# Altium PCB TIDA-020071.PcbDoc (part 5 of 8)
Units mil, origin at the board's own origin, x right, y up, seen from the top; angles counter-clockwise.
Board outline 5750 x 4050 mil, 6 copper layers (Top Layer, GND PLANE-1, SIGNAL LAYER, SIGNAL/POWER LAYER, GND PLANE-2, Bottom Layer), stack 59.616 mil thick; 776 components, 498 nets, 2205 pads, 871 vias.
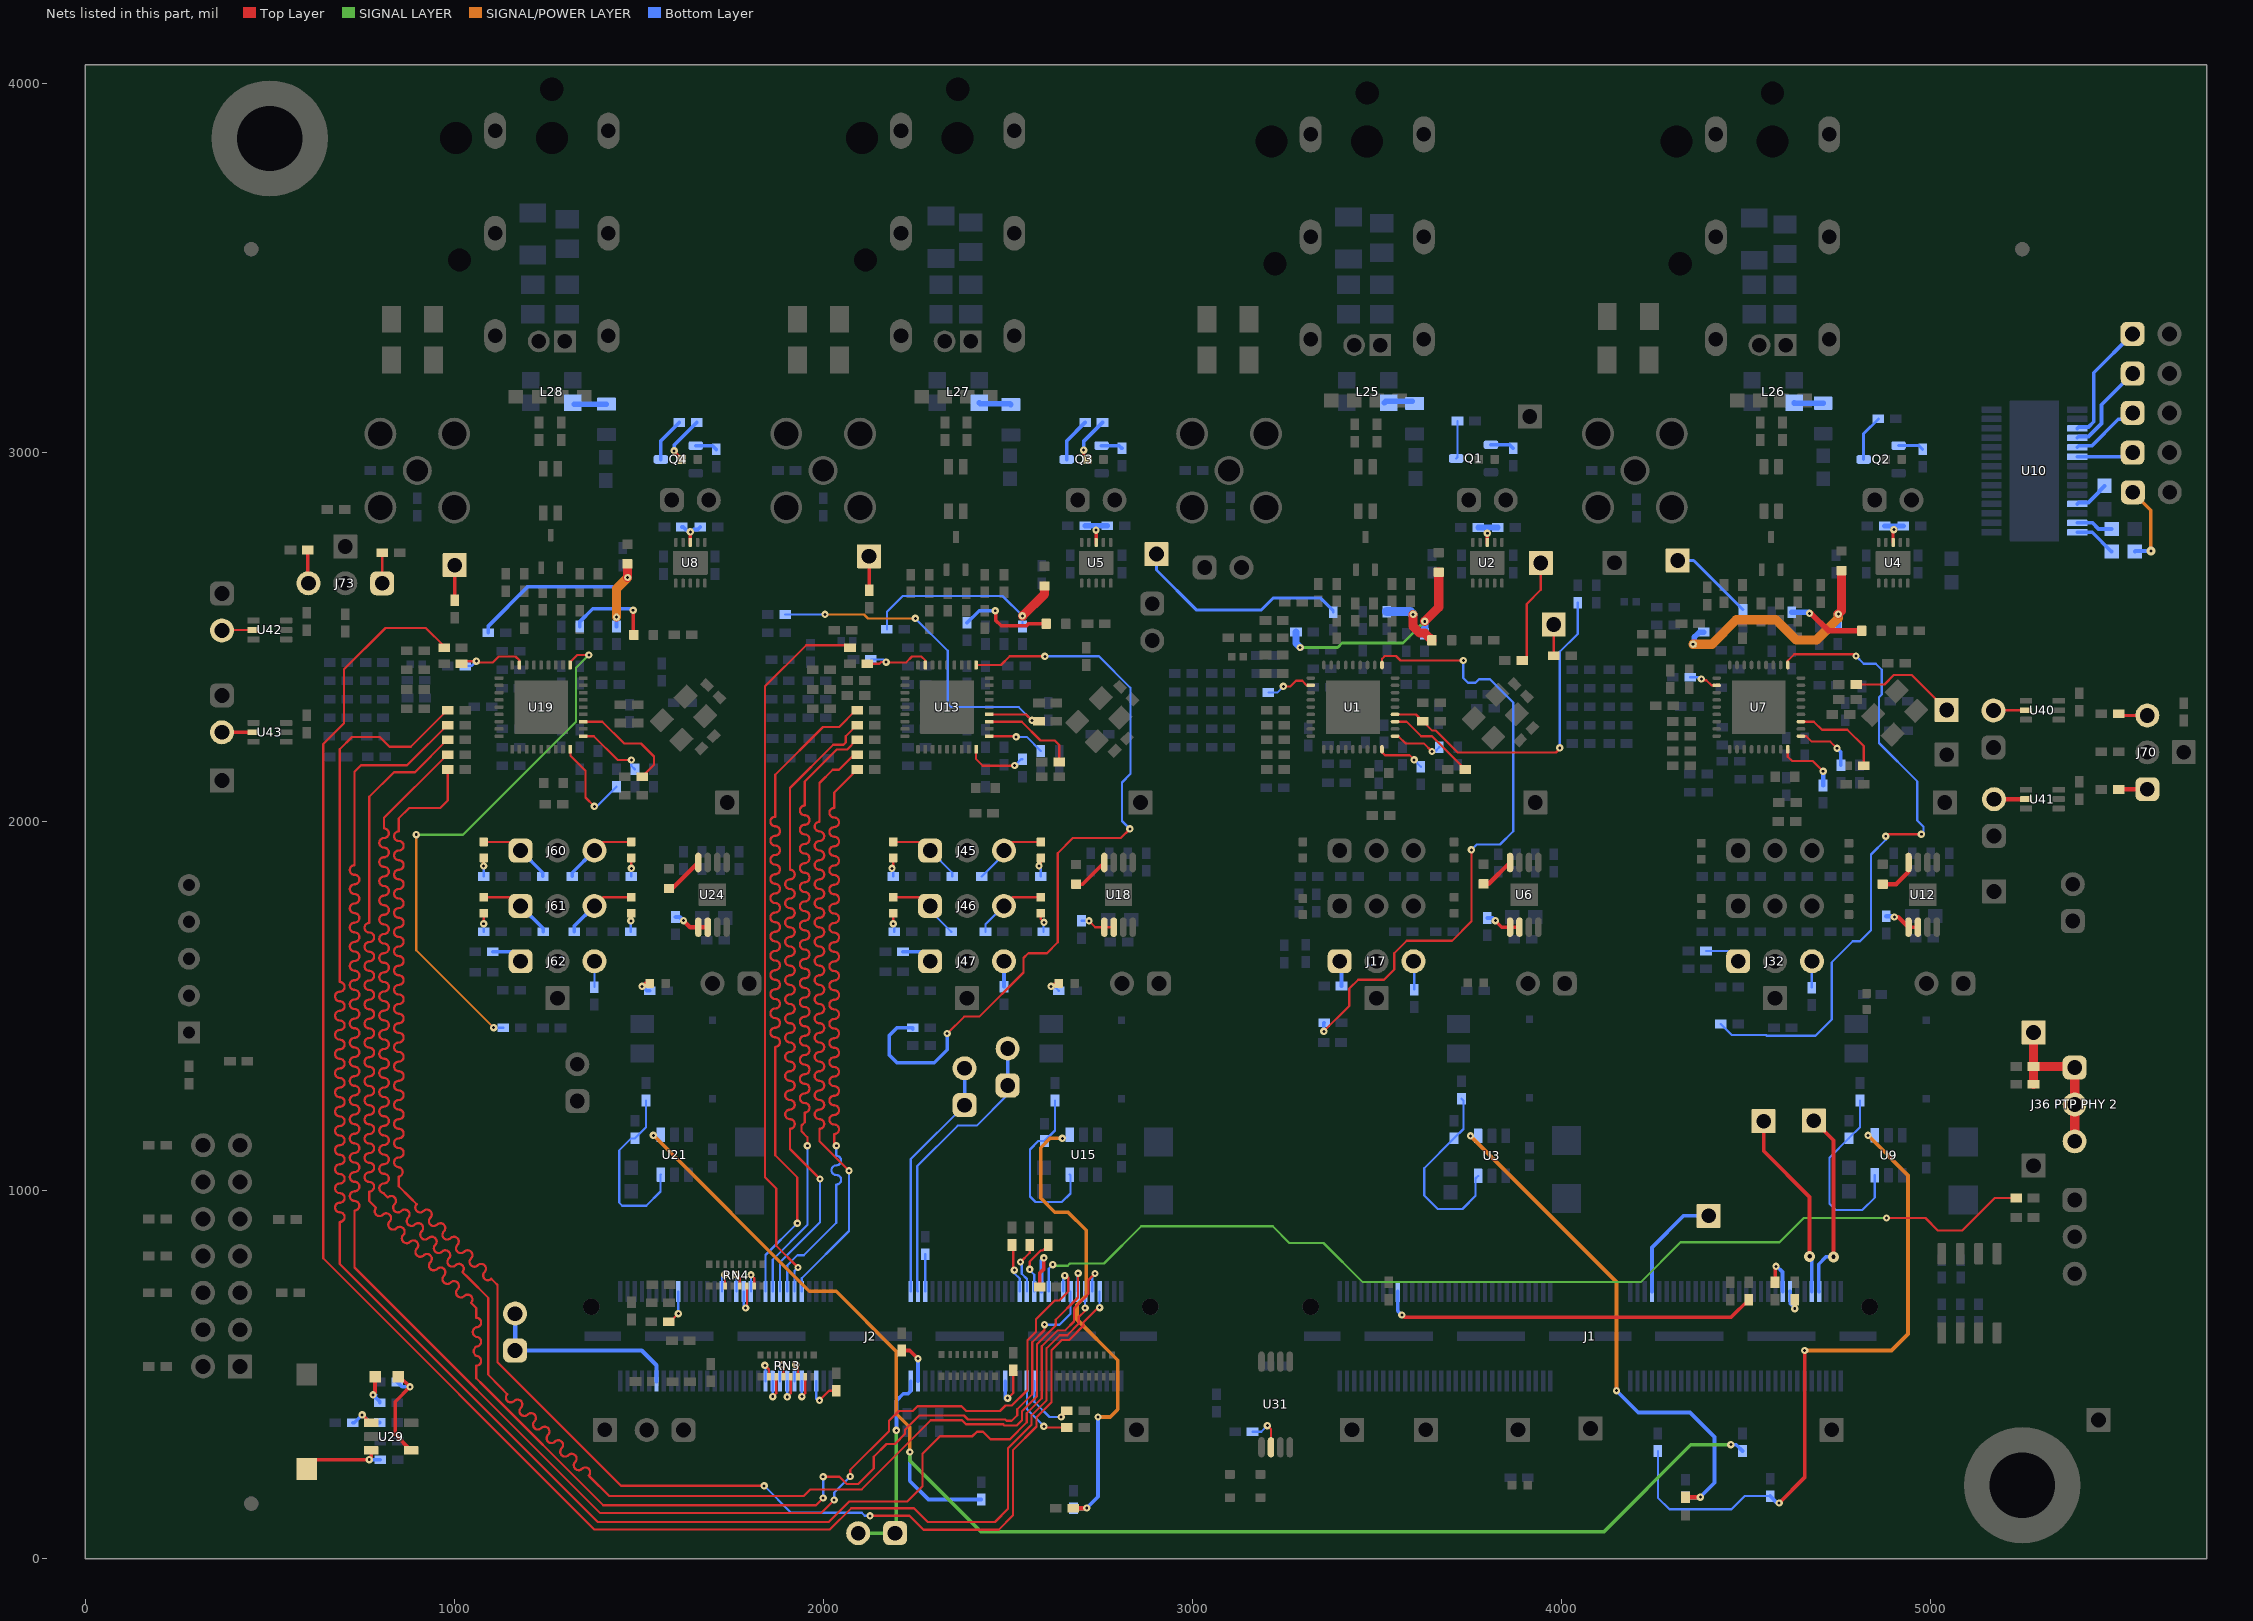
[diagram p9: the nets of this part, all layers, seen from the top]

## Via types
v1: diameter 20, hole 8, Top Layer to Bottom Layer, tented both sides, 637 vias
v2: diameter 30, hole 12, Top Layer to Bottom Layer, tented both sides, 105 vias
v3: diameter 19.68, hole 7.87, Top Layer to Bottom Layer, tented bottom, 68 vias
v4: diameter 19.68, hole 7.87, Top Layer to Bottom Layer, 25 vias
v5: diameter 24, hole 8, Top Layer to Bottom Layer, tented both sides, 24 vias
v6: diameter 19.68, hole 7.87, Top Layer to Bottom Layer, tented both sides, 12 vias

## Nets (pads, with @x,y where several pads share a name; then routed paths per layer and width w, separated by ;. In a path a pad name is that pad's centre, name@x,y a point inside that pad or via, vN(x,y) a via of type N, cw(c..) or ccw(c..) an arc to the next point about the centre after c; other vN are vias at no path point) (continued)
NetD19_2: D19.2 R133.1 | length 49
  Top Layer w6: v1(2618.13,1552) 2626.13,1560 D19.2@2638.49,1560
  Bottom Layer w6: v1(2618.13,1552) 2626.49,1552 R133.1@2638.49,1540
NetD20_1: D20.1 R131.2 | length 125.7
  Top Layer w10: v1(2705.89,3005.12) 2705.89,2990.8 D20.1@2716.69,2980
  Bottom Layer w10: v1(2705.89,3005.12) 2705.89,3028.65 R131.2@2757.24,3080
NetD21_1: D21.1 J45.1 R121.1 | length 204.5
  Top Layer w6: D21.1@2190,1943.31 2266.69,1943.31 J45.1@2290,1920
  Bottom Layer w6: J45.1@2290,1920 2350,1860 R121.1@2350,1850
NetD21_2: D21.2 R122.1 | length 54.7
  Top Layer w6: v1(2186.69,1871.65) 2190,1874.96 D21.2@2190,1900
  Bottom Layer w6: v1(2186.69,1871.65) 2190,1871.65 R122.1@2190,1850
NetD22_1: D22.1 R123.1 | length 54.3
  Top Layer w6: v1(2584.84,1878.62) 2590,1883.78 D22.1@2590,1900
  Bottom Layer w6: v1(2584.84,1878.62) 2584.84,1876.81 2590,1871.65 R123.1@2590,1850
NetD22_2: D22.2 J45.3 R124.1 | length 204.5
  Top Layer w6: J45.3@2490,1920 2513.31,1943.31 D22.2@2590,1943.31
  Bottom Layer w6: R124.1@2430,1850 2490,1910 J45.3@2490,1920
NetD23_1: D23.1 J46.1 R125.1 | length 203.4
  Top Layer w6: D23.1@2190,1793.31 2266.69,1793.31 J46.1@2290,1770
  Bottom Layer w6: J46.1@2290,1770 2290,1757.24 R125.1@2347.24,1700
NetD23_2: D23.2 R126.1 | length 51.1
  Top Layer w6: v1(2190,1721.65) D23.2@2190,1750
  Bottom Layer w6: v1(2190,1721.65) 2192.76,1718.9 R126.1@2192.76,1700
NetD24_1: D24.1 R127.1 | length 54
  Top Layer w6: D24.1@2590,1750 2590,1734.15 v1(2598.49,1725.66)
  Bottom Layer w6: R127.1@2597.24,1700 2597.24,1724.42 v1(2598.49,1725.66)
NetD24_2: D24.2 J46.3 R128.1 | length 200.4
  Top Layer w6: J46.3@2490,1770 2513.31,1793.31 D24.2@2590,1793.31
  Bottom Layer w6: R128.1@2440,1700 2440,1720 J46.3@2490,1770
NetD27_2: D27.2 R186.1 | length 49
  Top Layer w10: v1(1509.64,1552) 1517.64,1560 D27.2@1530,1560
  Bottom Layer w10: v1(1509.64,1552) 1521.63,1540 R186.1@1530,1540
NetD28_1: D28.1 R184.2 | length 133.8
  Top Layer w10: v1(1596.2,3003.44) 1596.2,3000.5 D28.1@1616.69,2980
  Bottom Layer w10: v1(1596.2,3003.44) 1596.2,3018.95 R184.2@1657.24,3080
NetD29_1: D29.1 J60.1 R174.1 | length 204.5
  Top Layer w6: D29.1@1080,1943.31 1156.69,1943.31 J60.1@1180,1920
  Bottom Layer w10: J60.1@1180,1920 1240,1860 R174.1@1240,1850
NetD29_2: D29.2 R175.1 | length 50
  Top Layer w6: v1(1080,1878.17) D29.2@1080,1900
  Bottom Layer w6: R175.1@1080,1850 v1(1080,1878.17)
NetD30_1: D30.1 R176.1 | length 50
  Top Layer w6: v1(1480,1871.65) D30.1@1480,1900
  Bottom Layer w6: R176.1@1480,1850 v1(1480,1871.65)
NetD30_2: D30.2 J60.3 R177.1 | length 204.5
  Top Layer w6: J60.3@1380,1920 1403.31,1943.31 D30.2@1480,1943.31
  Bottom Layer w10: R177.1@1320,1850 1320,1860 J60.3@1380,1920
NetD31_1: D31.1 J61.1 R178.1 | length 205.1
  Top Layer w6: D31.1@1080,1793.31 1156.69,1793.31 J61.1@1180,1770
  Bottom Layer w10: J61.1@1180,1770 1241.37,1708.63 R178.1@1241.37,1700
NetD31_2: D31.2 R179.1 | length 50
  Top Layer w6: v1(1080,1721.65) D31.2@1080,1750
  Bottom Layer w6: R179.1@1080,1700 v1(1080,1721.65)
NetD32_1: D32.1 R180.1 | length 50.6
  Top Layer w6: v1(1478.98,1729.53) 1480,1730.55 D32.1@1480,1750
  Bottom Layer w6: R180.1@1478.62,1700 1478.62,1729.17 v1(1478.98,1729.53)
NetD32_2: D32.2 J61.3 R181.1 | length 202.2
  Top Layer w6: J61.3@1380,1770 1403.31,1793.31 D32.2@1480,1793.31
  Bottom Layer w10: R181.1@1325.59,1700 1325.59,1715.59 J61.3@1380,1770
NetD41_1: D41.1 R263.1 U29.4 | length 289.3
  Top Layer w10: D41.1@848.62,494.09 852.56,494.09 v1(880.12,466.53) 840,426.42 840,337.63 U29.4@883.27,294.36
  Bottom Layer w10: R263.1@845.87,479.61 858.94,466.53 v1(880.12,466.53)
NetD41_2: D41.2 R262.1 | length 88.6
  Top Layer w10: v1(780,444.75) 785.63,450.38 D41.2@785.63,494.09
  Bottom Layer w10: v1@787.58,444.75 v1(780,444.75) 798.62,426.13 R262.1@798.62,423.09
NetJ1_7: J1.7 MCASP1_AXR5.1 | length 514.2
  Top Layer w10: MCASP1_AXR5.1@4685.04,1187.99 4738.37,1134.66 v2(4738.37,818.9)
  Bottom Layer w10: J1.7@4699.21,725 4698,726.21 4698,798.9 4718,818.9 v2(4738.37,818.9)
NetJ1_9: J1.9 MCASP1_AXR6.1 | length 515.6
  Top Layer w10: MCASP1_AXR6.1@4549,1186.51 4549,1105.61 4673.34,981.27 v2(4673.34,820)
  Bottom Layer w10: v2(4673.34,820) 4679.53,813.81 J1.9@4679.53,725
NetJ1_15: J1.15 R285.1 | length 76.3
  Top Layer w10: v1(4633.27,678.38) R285.1@4633.27,702.76
  Bottom Layer w10: J1.15@4620.47,725 4621.48,724 4621.48,692.16 4633.27,680.37 v1(4633.27,678.38)
NetJ1_17: J1.17 R4.1 | length 121.4
  Top Layer w10: R4.1@4580,750 4580,790.76 v1(4582.5,793.25)
  Bottom Layer w10: v1(4582.5,793.25) 4584.7,793.25 4599.98,777.97 4599.98,725.81 J1.17@4600.79,725
NetJ1_53: J1.53 MCASP0_AXR5.1 | length 308.5
  Bottom Layer w10: J1.53@4246.46,725 4246.46,844.53 4331.92,930 MCASP0_AXR5.1@4400,930
NetJ1_103: J1.103 R5.1 | length 1030.3
  Top Layer w10: v1(3568.53,661.42) 3574.86,655.09 4460.6,655.09 R5.1@4508.27,702.76
  Bottom Layer w10: J1.103@3557.48,725 3557.48,672.47 v1(3568.53,661.42)
NetJ2_21: J2.21 R350.1 | length 2918.7
  Top Layer w6: v1(4881.97,924.17) 4987.55,924.17 5021.72,890 5086.77,890 5175,978.23 R350.1@5233.23,978.23
  SIGNAL LAYER w6: v1(2622.33,797.67) 2625,795 2663.08,795 2669.02,800.94 2761.14,800.94 2861.9,901.7 3218.3,901.7 3263.5,856.5 3356.35,856.5 3462.45,750.4 4215.8,750.4 4323.65,858.25 4591.88,858.25 4657.79,924.17 v1(4881.97,924.17)
  Bottom Layer w6: J2.21@2611.42,725 2611.42,786.76 v1(2622.33,797.67)
NetJ2_23: J2.23 R286.1 | length 177.3
  Top Layer w10: R286.1@2587.32,737.2 2587.32,775.3 2598.22,786.19 v1(2598.22,816.17)
  Bottom Layer w10: J2.23@2591.73,725 2591.73,809.68 v1(2598.22,816.17)
NetJ2_25: J2.25 R287.1 | length 155.9
  Top Layer w6: v1(2560,785) 2560,806.23 2589.94,836.17 2595.11,836.17 R287.1@2610,851.05
  Bottom Layer w6: v1(2560,785) 2558.68,783.68 2572.05,770.31 J2.25@2572.05,725
NetJ2_26: J2.26 R355.2 | length 169
  Top Layer w6: v1(2645.1,384.91) 2660.63,400.45 R355.2@2660.63,401.4
  Bottom Layer w6: J2.26@2572.05,482.01 2572.05,426.05 2613.19,384.91 v1(2645.1,384.91)
NetJ2_27: J2.27 R288.1 | length 143.6
  Top Layer w6: v1(2535,805) 2560,830 R288.1@2560,851.05
  Bottom Layer w6: v1(2535,805) 2538,802 2538,773.08 2552.36,758.71 J2.27@2552.36,725
NetJ2_28: J2.28 R354.2 | length 198.5
  Top Layer w6: v1(2598.03,359.6) 2601.54,356.1 R354.2@2660.63,356.1
  Bottom Layer w6: J2.28@2552.36,482.01 2552.36,405.76 v1@2593.52,364.6
NetJ2_29: J2.29 R364.1 | length 134.8
  Top Layer w6: R364.1@2511.62,851.05 2515,847.67 2515,785.92 v1(2518,782.92)
  Bottom Layer w6: v1(2518,782.92) 2518,774.69 2532.68,760.01 J2.29@2532.68,725
NetJ2_34: J2.34 R2.1 | length 139
  Top Layer w6: v1(2500,436) 2501,436 2515,450 R2.1@2515,511.38
  Bottom Layer w10: J2.34@2493.31,482.01 2493.31,434.93 2493.85,435.47 2496.81,432.52 2500,435.71 v1(2500,436)
NetJ2_55: J2.55 R362.1 | length 101.4
  Bottom Layer w6: J2.55@2276.77,725 R362.1@2276.77,826.38
NetJ2_57: J2.57 MCASP0_ACLKX.1 MCASP0_ACLKX.2 | length 790.8
  Bottom Layer w6: J2.57@2257.09,725 2254.96,727.13 2254.96,1064.89 2364.59,1174.52 2415.91,1174.52 2500,1258.61 MCASP0_ACLKX.1@2500,1283.36
  Bottom Layer w10: MCASP0_ACLKX.1@2500,1283.36 MCASP0_ACLKX.2@2500,1383.36
NetJ2_58: J2.58 R363.2 | length 114
  Top Layer w10: R363.2@2213.11,565.05 2234.92,565.05 v1(2257.09,542.88)
  Bottom Layer w10: J2.58@2257.09,482.01 v1(2257.09,542.88)
NetJ2_59: J2.59 MCASP0_AFSX.1 MCASP0_AFSX.2 | length 665.5
  Bottom Layer w6: J2.59@2237.4,725 2237.4,1083.98 MCASP0_AFSX.1@2383.42,1230
  Bottom Layer w10: MCASP0_AFSX.1@2383.42,1230 MCASP0_AFSX.2@2383.42,1330
NetJ2_60: J2.60 MCASP1_AFSX.1 MCASP1_AFSX.2 | length 567.3
  SIGNAL LAYER w10: MCASP1_AFSX.2@2095,70 MCASP1_AFSX.1@2195,70 2198.43,73.43 v1(2198.43,348.85)
  Bottom Layer w10: 2198.43,379.14 v1(2198.43,348.85) 2198.72,349.14 2198.72,429.63 2217.1,448 2229.89,448 2237.4,455.52 J2.60@2237.4,482.01
NetJ2_66: J2.66 R356.2 | length 114.9
  Top Layer w6: v1(1990,430) 2015.98,455.98 R356.2@2035.59,455.98
  Bottom Layer w6: J2.66@1981.5,482.01 1981.5,433.34 1984.84,430 v1(1990,430)
NetJ2_103: J2.103 R1.1 | length 98.9
  Top Layer w6: R1.1@1581.5,642.99 1585.37,642.99 v1(1607.48,665.1)
  Bottom Layer w6: v1@1603.6,665.1 v1(1607.48,665.1) J2.103@1607.48,725
NetJ2_110: J2.110 MCASP1_ACLKX.1 MCASP1_ACLKX.2 | length 543.1
  Bottom Layer w12: MCASP1_ACLKX.2@1165,665 MCASP1_ACLKX.1@1165,565 1508.62,565 1548.43,525.2 J2.110@1548.43,482.01
NetJ11_1: J11.1 R414.2 | length 95
  Top Layer w10: J11.1@1001.47,2693.53 1001.87,2693.13 R414.2@1001.87,2598.65
NetJ17_1: J17.1 R23.2 | length 69
  Bottom Layer w10: J17.1@3400,1620 3405,1615 R23.2@3405,1553.1
NetJ17_3: J17.3 R23-2.1 | length 77.7
  Bottom Layer w6: J17.3@3600,1620 3601.93,1618.07 R23-2.1@3601.93,1543.12
NetJ18_1: J18.1 R409.2 | length 92.7
  Top Layer w10: J18.1@2115.98,2717.61 J18.1@2116.38,2717.21 ; R409.2@2125,2625.03 J18.1@2125,2717.21
NetJ24_1: J24.1 R332.2 | length 280.4
  Top Layer w6: R332.2@3907,2435.02 3907,2588.43 3945.15,2626.57 J24.1@3945.15,2699.6
NetJ25_1: J25.1 U10.3 | length 333.9
  Bottom Layer w10: U10.3@5398.97,3064.11 5402.83,3067.97 5429.49,3067.97 5443.68,3082.17 5443.68,3215.3 J25.1@5548.71,3320.34
NetJ26_1: J26.1 U10.4 | length 252
  Bottom Layer w10: U10.4@5398.97,3038.52 5402.83,3042.38 5429.49,3042.38 5464.58,3077.48 5464.58,3128.13 J26.1@5549.17,3212.72
NetJ27_1: J27.1 U10.5 | length 188.9
  Bottom Layer w10: U10.5@5398.97,3012.93 5402.83,3016.79 5438.24,3016.79 5510.11,3088.66 5531.66,3088.66 J27.1@5549.21,3106.22
NetJ32_1: J32.1 R76.2 | length 99
  Bottom Layer w6: R76.2@4392.6,1647.94 4452.06,1647.94 J32.1@4480,1620
NetJ32_3: J32.3 R76-2.1 | length 71.7
  Bottom Layer w6: R76-2.1@4679.2,1548.62 4679.2,1619.2 J32.3@4680,1620
NetJ33_1: J33.1 U10.6 | length 154.9
  Bottom Layer w10: U10.6@5398.97,2987.34 5399.03,2987.4 5537.91,2987.4 J33.1@5549.21,2998.7
NetJ34_1: J34.1 R220.1 | length 222.9
  SIGNAL/POWER LAYER w10: J34.1@5549.62,2890.97 5598.33,2842.25 v5(5598.33,2731.68)
  Bottom Layer w10: R220.1@5555.32,2730.7 5556.3,2731.68 v5(5598.33,2731.68)
"NetJ36 PTP PHY 2_1": "J36 PTP PHY 2.1" "J36 PTP PHY 2.2" "J36 PTP PHY 2.3" "J63_1 PTP PHY 2.1" R352.2 R353.1 | length 452.5
  Top Layer w25: R353.1@5280.47,1286.9 R352.2@5280.47,1334.66 ; 5280.47,1426.9 R352.2@5280.47,1334.66 ; 5391.85,1131.9 5391.85,1231.9 5391.85,1331.9 5389.09,1334.66 R352.2@5280.47,1334.66
NetJ47_1: J47.1 R129.2 | length 84.3
  Bottom Layer w10: R129.2@2216.3,1645.59 2264.41,1645.59 J47.1@2290,1620
NetJ47_3: J47.3 R129-2.1 | length 69.3
  Bottom Layer w10: R129-2.1@2490,1550.67 J47.3@2490,1620
NetJ62_1: J62.1 R182.2 | length 86.3
  Bottom Layer w10: R182.2@1104.31,1645.59 1154.41,1645.59 J62.1@1180,1620
NetJ62_3: J62.3 R182-2.1 | length 70
  Bottom Layer w6: R182-2.1@1380,1550 J62.3@1380,1620
NetJ70_1: J70.1 R307.1 | length 77.7
  Top Layer w12: R307.1@5511.48,2085.38 5511.9,2085.8 5588.44,2085.8 J70.1@5588.86,2086.22
NetJ70_3: J70.3 R308.1 | length 79.2
  Top Layer w8: R308.1@5511.48,2290.63 5515.89,2286.22 J70.3@5588.86,2286.22
NetJ71_2: J71.2 U40.5 | length 88.9
  Top Layer w6: J71.2@5171.67,2299.31 5172.79,2300.42 U40.5@5260.11,2300.42
NetJ72_2: J72.2 U41.5 | length 86.8
  Top Layer w12: J72.2@5173.35,2059.31 5173.53,2059.49 U41.5@5260.11,2059.49
NetJ73_1: J73.1 R310.1 | length 83
  Top Layer w6: J73.1@805,2644.38 R310.1@805,2727.33
NetJ73_3: J73.3 R311.1 | length 90.9
  Top Layer w10: R311.1@603.57,2734.65 603.57,2645.81 J73.3@605,2644.38
NetJ74_2: J74.2 U42.5 | length 86.2
  Top Layer w6: J74.2@370.45,2516.63 371.71,2517.9 U42.5@456.15,2517.9
NetJ75_2: J75.2 U43.5 | length 85.7
  Top Layer w10: J75.2@370.45,2240.5 U43.5@456.15,2240.5
NetL10_2: L10.2 R41.2 | length 174
  Top Layer w25: v1(3598.84,2560) 3598.84,2554.87 3598.53,2554.57 3598.53,2528.06 3617.28,2509.31 3630.69,2509.31 L10.2@3650,2490
  Bottom Layer w25: R41.2@3527.28,2567.62 3591.22,2567.62 v1(3598.84,2560)
NetL11_2: L11.2 R39.2 R40.2 | length 596
  Top Layer w25: v1(3630.53,2541.31) 3668.38,2579.16 L11.2@3668.38,2674.38
  SIGNAL LAYER w8: v1(3292.76,2470.38) 3394.46,2470.38 3406.48,2482.4 3571.62,2482.4 v1(3630.53,2541.31)
  Bottom Layer w20: R40.2@3281.38,2512.28 3281.38,2481.76 v1(3292.76,2470.38) ; R39.2@3630,2507.24 v1@3630,2540.78
NetL13_2: L13.2 R94.2 | length 210.6
  Top Layer w15: v1(4673.34,2562.83) 4677.3,2562.83 4724.13,2516.01 4724.13,2515.78 L13.2@4814.72,2515.78
  Bottom Layer w15: R94.2@4625,2565.98 4670.2,2565.98 v1(4673.34,2562.83)
NetL14_2: L14.2 R92.2 R93.2 | length 686.6
  Top Layer w25: v1(4751.37,2560.9) 4760,2569.53 L14.2@4760,2678.75
  SIGNAL/POWER LAYER w25: v1(4357.8,2479.2) 4408.9,2479.2 4475.01,2545.31 4582.5,2545.31 4637.3,2490.5 4692.22,2490.5 4751.37,2549.65 v1(4751.37,2560.9)
  Bottom Layer w15: v1(4357.8,2479.2) 4361.48,2482.88 4361.48,2498.77 4374.98,2512.28 R93.2@4386.38,2512.28 ; R92.2@4750,2527.24 4750.68,2527.93 4750.68,2560.21 v1(4751.37,2560.9)
NetL16_2: L16.2 R147.2 | length 262
  Top Layer w10: v1(2466.45,2570) 2468,2568.45 2468,2543.72 2482.43,2529.29 2551.18,2529.29 2556.52,2534.62 L16.2@2604.85,2534.62
  Bottom Layer w10: R147.2@2390,2537.24 2422.76,2570 v1(2466.45,2570)
NetL17_2: L17.2 R145.2 R146.2 | length 589.5
  Top Layer w25: v1(2540,2556.29) 2541.29,2556.29 2600,2615 L17.2@2600,2637.01
  Bottom Layer w6: R146.2@2172.76,2520 2172.76,2566.78 2215.98,2610 2486.29,2610 v1(2540,2556.29) R145.2@2540,2527.24
NetL18_2: L18.2 R198.2 R199.2 | length 627.9
  Top Layer w10: v1@1469.69,2660.31 v1(1470,2660)
  Top Layer w25: v1@1469.69,2660.31 L18.2@1469.69,2692.13
  SIGNAL/POWER LAYER w25: v1(1440,2552.83) 1440,2630 v1(1470,2660)
  Bottom Layer w10: R199.2@1092.76,2510 1092.76,2528.89 1198.87,2635 1445,2635 v1(1470,2660) ; R198.2@1440,2527.24 v1(1440,2552.83)
NetL19_2: L19.2 R200.2 | length 241.6
  Top Layer w10: v1(1485,2571.3) 1485,2506.47 L19.2@1486.85,2504.62
  Bottom Layer w10: R200.2@1340,2527.24 1340,2539.72 1375.9,2575.62 1480.68,2575.62 v1(1485,2571.3)
NetL21_1: L21.1 U6.8 | length 95.5
  Top Layer w12: L21.1@3790,1830 3804.02,1830 U6.8@3861.61,1887.6
NetL22_1: L22.1 U12.8 | length 108.7
  Top Layer w12: L22.1@4871.61,1829.25 4908.09,1829.25 4941.61,1862.78 U12.8@4941.61,1887.6
NetL23_1: L23.1 U18.8 | length 100.8
  Top Layer w10: L23.1@2685.51,1829.13 2703.62,1829.13 U18.8@2762.09,1887.6
NetL24_1: L24.1 U24.8 | length 109
  Top Layer w12: L24.1@1581.79,1817.16 1591.18,1817.16 U24.8@1661.61,1887.6
NetL25_2: L25.2 R168.1 | length 77.1
  Bottom Layer w15: L25.2@3521.09,3133.49 3525,3137.4 R168.1@3596.59,3137.4
NetL26_2: L26.2 R183.1 | length 79.3
  Bottom Layer w15: L26.2@4631.59,3133.49 4632.13,3132.95 4709.9,3132.95 R183.1@4710.44,3132.4
NetL27_2: L27.2 R187.1 | length 87.4
  Bottom Layer w15: L27.2@2423.09,3133.49 2425.34,3131.24 2506.41,3131.24 R187.1@2508.66,3128.99
NetL28_2: L28.2 R204.1 | length 92.6
  Bottom Layer w4: L28.2@1321.65,3133.49 L28.2@1325.11,3130.03
  Bottom Layer w15: L28.2@1325.11,3130.03 R204.1@1412.78,3130.03
NetLED_1_2_1: LED_1_2.1 R367.2 | length 295.2
  Top Layer w6: R367.2@4799.99,2370 4876.36,2370 4902.51,2396.14 4949.86,2396.14 LED_1_2.1@5045,2301
NetQ1_1: Q1.1 R26.1 | length 64.1
  Bottom Layer w10: Q1.1@3810,3020 3860,3020 R26.1@3870,3010
NetQ1_3: Q1.3 R25.1 | length 103
  Bottom Layer w6: Q1.3@3715.51,2982.6 3719.38,2986.46 R25.1@3719.38,3084
NetQ2_1: Q2.1 R79.1 | length 69.7
  Bottom Layer w8: Q2.1@4914.49,3017.4 4969.84,3017.4 R79.1@4980,3007.24
NetQ2_3: Q2.3 R78.1 | length 126.6
  Bottom Layer w8: Q2.3@4820,2980 4820,3050 R78.1@4860,3090
NetQ3_1: Q3.1 R132.1 | length 58.6
  Bottom Layer w10: Q3.1@2754.49,3017.4 2802.6,3017.4 R132.1@2810,3010
NetQ3_3: Q3.3 R131.1 | length 120.7
  Bottom Layer w10: Q3.3@2660,2980 2660,3030 R131.1@2710,3080
NetQ4_1: Q4.1 R185.1 | length 59.7
  Bottom Layer w10: Q4.1@1654.49,3017.4 1699.84,3017.4 R185.1@1710,3007.24
NetQ4_3: Q4.3 R184.1 | length 120.7
  Bottom Layer w10: Q4.3@1560,2980 1560,3030 R184.1@1610,3080
NetR3_2: R3.2 R10.1 U3.4 | length 1431.1
  Top Layer w12: R3.2@4337.29,167.76 v1(4377.32,167.76)
  SIGNAL/POWER LAYER w10: v1(3754.33,1146.64) 4150,750.97 v1(4150,456.28)
  Bottom Layer w10: v1(4150,456.28) 4209.06,397.23 4349.34,397.23 4415.89,330.68 4415.89,206.32 v1(4377.32,167.76)
  Bottom Layer w12: R10.1@4337.29,167.76 v1(4377.32,167.76)
NetR9_2: R9.2 R63.1 U9.4 | length 1814.6
  Top Layer w10: v1(4591.18,151.81) 4660,220.63 v1(4660,565)
  SIGNAL/POWER LAYER w10: v1(4660,565) 4895.24,565 4940.24,610 4940.24,1039.68 v1(4831.65,1148.27)
  Bottom Layer w6: R9.2@4262.29,292.76 4262.29,166.32 4293.61,135 4461.88,135 4497.39,170.51 R63.1@4566.73,170.51
  Bottom Layer w10: R63.1@4566.73,170.51 4585.43,151.81 v1(4591.18,151.81)
NetR11_1: R11.1 R12.2 U3.3 | length 534.5
  Bottom Layer w6: R11.1@3730,1247.51 3735.62,1241.89 3735.62,1165.62 R12.2@3710,1140 3629.4,1059.4 3629.4,984.9 3665.7,948.6 3732.5,948.6 3768.17,984.27 3768.17,1002.74 3768.17,1005.89 3768.17,1031.34 U3.3@3775.2,1038.37
NetR13_1: R13.1 R14.2 U2.8 | length 95.5
  Top Layer w10: U2.8@3800,2755.12 v1(3800,2780)
  Bottom Layer w15: R13.1@3775.6,2795.57 3794.43,2795.57 ; v1(3800,2780) 3800,2790 3794.43,2795.57 ; R14.2@3828.35,2795.57 3794.43,2795.57
NetR44_1: R44.1 U6.1 U6.2 | length 97.5
  Top Layer w10: v1(3821.65,1730) 3839.25,1712.4 U6.1@3861.61,1712.4 U6.2@3887.2,1712.4
  Bottom Layer w10: R44.1@3800,1737.24 3814.41,1737.24 v1(3821.65,1730)
NetR45_2: R45.2 R116.1 U15.4 | length 1301.4
  Top Layer w12: R45.2@2677.73,137.61 2713.81,137.61 v1(2714.41,138.21)
  SIGNAL/POWER LAYER w10: v1(2648.42,1140) 2614.6,1140 2589.5,1114.9 2589.5,978.47 2628.02,939.96 2663.64,939.96 2712.87,890.72 2712.87,714.26 2688,689.39 2688,649.17 2798.63,538.54 2798.63,405.47 2778.16,385 v1(2745,385)
  Bottom Layer w10: v1(2714.41,138.21) 2745,168.8 v1(2745,385)
  Bottom Layer w12: R116.1@2678.58,137.61 2713.81,137.61 v1(2714.41,138.21)
NetR46_1: R46.1 U1.10 | length 1740.6
  Top Layer w6: v1(3357.09,1430) 3425.95,1498.87 3425.95,1545.95 3450,1570 3520,1570 3547.83,1597.83 3547.83,1642.01 3581.68,1675.86 3704.65,1675.86 3757.01,1728.22 v1(3757.01,1922.14) ; U1.10@3514.57,2422.91 3515,2423.35 3515,2440 3522.33,2447.33 3552.67,2447.33 3565,2435 v1(3735,2435)
  Bottom Layer w6: v1(3735,2435) 3735,2387.84 3747.84,2375 3768.28,2375 3777.61,2384.32 3807.25,2384.32 3870.52,2321.05 3870.52,1972.52 3834.3,1936.3 3771.17,1936.3 v1(3757.01,1922.14)
  Bottom Layer w10: v1(3357.09,1430) 3357.09,1452.43 R46.1@3357.76,1453.1
NetR47_1: R47.1 U1.3 | length 243.6
  Top Layer w6: U1.3@3550,2269.37 3581.3,2269.37 3620.67,2230 3650,2230 R47.1@3740,2140
NetR50_1: R50.1 U1.1 | length 142.1
  Top Layer w6: U1.1@3550,2230 3558.87,2230 3578.37,2210.5 3627.85,2210.5 v1(3650,2188.35)
  Bottom Layer w6: v1(3650,2188.35) 3658.35,2188.35 R50.1@3670,2200
NetR51_1: R51.1 U1.36 | length 130.1
  Top Layer w6: U1.36@3514.57,2194.57 3514.57,2186.3 3522.68,2178.19 3589.44,2178.19 v1(3601.93,2165.7)
  Bottom Layer w6: v1(3601.93,2165.7) 3601.93,2165.31 R51.1@3620,2147.24
NetR60_2: R60.2 R61.2 U1.4 | length 909.5
  Top Layer w6: U1.4@3550,2289.05 3606.5,2289.05 R60.2@3625,2270.55 3649.8,2245.75 3659.84,2245.75 3719.68,2185.91 3986,2185.91 v1@3998.38,2198.28
  Bottom Layer w6: v1(3996.38,2198.28) 3996.38,2458.57 4045,2507.19 4045,2553.55 R61.2@4045,2591.38
NetR62_2: R62.2 R169.1 U21.4 | length 3946.4
  SIGNAL LAYER w10: v1(2235,290) 2235,267.11 2428.67,73.43 4115.33,73.43 4351.62,309.72 v1(4460,309.72)
  SIGNAL/POWER LAYER w10: v1(1540,1148.27) 1540,1148.13 1962.4,725.73 2035.38,725.73 2198.43,562.68 2198.43,393.69 2235,357.12 v1(2235,290)
  Bottom Layer w10: v1(2235,290) 2235,211.71 2285.47,161.23 R169.1@2428.58,161.23 ; v1(4460,309.72) 4474.76,309.72 R62.2@4491.73,292.76
NetR64_1: R64.1 R65.2 U9.3 | length 518.4
  Bottom Layer w6: R64.1@4810,1242.76 4810,1170 R65.2@4780,1140 4727.32,1087.32 4727.32,962.97 4744.63,945.67 4816.27,945.67 4850,979.4 U9.3@4850,1040
NetR66_1: R66.1 R67.2 U4.8 | length 85.6
  Top Layer w8: U4.8@4900,2755.12 4900,2788.27 v1(4901.73,2790)
  Bottom Layer w14: R66.1@4877.32,2799.76 R67.2@4927.32,2799.76
NetR97_1: R97.1 U12.1 U12.2 | length 98
  Top Layer w10: U12.1@4941.61,1712.4 U12.2@4967.2,1712.4
  Top Layer w12: v1(4903.27,1740) 4914.02,1740 U12.1@4941.61,1712.4
  Bottom Layer w12: R97.1@4881.61,1742.4 4900.87,1742.4 v1(4903.27,1740)
NetR99_1: R99.1 U7.10 | length 1791.3
  Top Layer w6: U7.10@4614.57,2422.91 4614.57,2434.57 4632,2452 4794.45,2452 v1(4799.27,2447.19) ; v1(4879.9,1958.85) 4885.22,1964.17 v1(4976.32,1964.17)
  Bottom Layer w6: R99.1@4432.76,1450 4462.76,1420 4555.46,1420 4557.28,1418.19 4689.26,1418.19 4733.27,1462.2 4733.27,1616.97 4790.46,1674.16 4809.87,1674.16 4840.12,1704.41 4840.12,1909.25 4879.9,1949.04 v1(4879.9,1958.85) ; v1(4799.27,2447.19) 4820.37,2426.09 4853,2426.09 4868.98,2410.11 4868.98,2342.79 4861.61,2335.43 4861.61,2211.39 4965.52,2107.48 4965.52,2001.26 4982.21,1984.57 4982.21,1970.06 v1(4976.32,1964.17)
NetR100_1: R100.1 U7.3 | length 250.6
  Top Layer w6: U7.3@4650,2269.37 4685.04,2269.37 4707.21,2247.2 4775.93,2247.2 4820,2203.13 R100.1@4820,2150
NetR103_1: R103.1 U7.1 | length 162
  Top Layer w6: U7.1@4650,2230 4664.52,2230 4679.2,2215.31 4729.57,2215.31 v1(4747.61,2197.28)
  Bottom Layer w10: v1(4747.61,2197.28) 4758.35,2186.54 R103.1@4758.35,2150.87
NetR104_1: R104.1 U7.36 | length 170.6
  Top Layer w6: U7.36@4614.57,2194.57 4614.57,2174.37 4626.18,2162.76 4682.24,2162.76 v1(4710,2135)
  Bottom Layer w12: R104.1@4710,2096.37 v1(4710,2135)
NetR117_1: R117.1 R118.2 U15.3 | length 475.7
  Bottom Layer w6: R117.1@2628.49,1242.76 2628.49,1161.25 R118.2@2600,1132.76 2583.34,1132.76 2560.5,1109.91 2560.5,982.47 2575.65,967.32 2647.04,967.32 2670.2,990.49 2670.2,1040.02 U15.3@2668.49,1041.73
NetR119_1: R119.1 R120.2 U5.8 | length 104.8
  Top Layer w10: v1(2739.45,2788.38) 2740,2787.83 U5.8@2740,2755.12
  Bottom Layer w15: R119.1@2710,2800 2739.45,2800 ; v1(2739.45,2788.38) 2740,2788.93 2740,2800 R120.2@2770,2800
NetR150_1: R150.1 U18.1 U18.2 | length 95
  Top Layer w6: v1(2720.67,1729.38) 2737.65,1712.4 U18.1@2762.09,1712.4 U18.2@2787.68,1712.4
  Bottom Layer w6: R150.1@2700,1730 2720.06,1730 v1(2720.67,1729.38)
NetR152_1: R152.1 U13.10 | length 2107.3
  Top Layer w6: v1(2336.22,1424.05) 2382.17,1470 2423.11,1470 2542.8,1589.69 2542.8,1628.62 2556.18,1642 2606.41,1642 2635.66,1671.25 2635.66,1913.04 2676.74,1954.12 2806.83,1954.12 v1(2831.42,1978.71) ; U13.10@2414.57,2422.91 2481.87,2422.91 2505.51,2446.56 v1(2600.96,2446.56)
  Bottom Layer w6: v1(2600.96,2446.56) 2747.34,2446.56 2832.62,2361.28 2832.62,2127.38 2810,2104.76 2810,2000.14 v1(2831.42,1978.71)
  Bottom Layer w10: R152.1@2242.76,1435.84 R152.1@2242.76,1440 2200,1440 2178.98,1418.98 2178.98,1366.02 2200,1345 2301,1345 2336.22,1380.22 v1(2336.22,1424.05)
NetR153_1: R153.1 U13.3 | length 262.3
  Top Layer w6: U13.3@2450,2269.37 2538.19,2269.37 2589.21,2218.35 2627.7,2218.35 2640,2206.04 R153.1@2640,2160
NetR156_1: R156.1 U13.1 | length 156.6
  Top Layer w6: U13.1@2450,2230 2521.26,2230 v1(2523.11,2228.15)
  Bottom Layer w6: v1(2523.11,2228.15) 2551.85,2228.15 R156.1@2590,2190
NetR157_1: R157.1 U13.36 | length 167.1
  Top Layer w6: U13.36@2414.57,2194.57 2414.57,2167.85 2432.41,2150 2518.4,2150 v1(2518.81,2150.41)
  Bottom Layer w6: v1(2518.81,2150.41) 2518.81,2150.22 2519.03,2150 2536.27,2167.24 R157.1@2540,2167.24
NetR166_2: R166.2 R167.2 U13.4 | length 1014.1
  Top Layer w6: U13.4@2450,2289.05 2549.7,2289.05 v1(2565.89,2272.86) 2568.65,2270.11 R166.2@2584.84,2270.11
  SIGNAL/POWER LAYER w6: v1(2005,2560) 2110.56,2560 2121.34,2549.22 v1(2250,2549.22)
  Bottom Layer w6: R167.2@1897.24,2560 v1(2005,2560) ; v1(2250,2549.22) 2337.64,2461.58 2337.64,2318.49 2347.39,2308.74 2530.02,2308.74 v1(2565.89,2272.86)
NetR170_1: R170.1 R171.2 U21.3 | length 490.5
  Bottom Layer w6: R170.1@1520,1242.76 1520,1170 R171.2@1490,1140 1479.83,1140 1447.24,1107.42 1447.24,965.86 1455.6,957.5 1520.9,957.5 1559.34,995.94 1559.34,1041.07 U21.3@1560,1041.73
NetR172_1: R172.1 R173.2 U8.8 | length 89.5
  Top Layer w10: U8.8@1640,2755.12 v1(1640,2783.6)
  Bottom Layer w10: R172.1@1617.11,2796.89 1621.04,2796.89 1632.42,2785.52 1640.79,2785.52 1642.71,2783.6 1649.18,2790.08 1660.3,2790.08 R173.2@1667.11,2796.89
NetR203_1: R203.1 U24.1 U24.2 | length 98.6
  Top Layer w12: v1(1621.65,1730) 1639.25,1712.4 U24.1@1661.61,1712.4 U24.2@1687.2,1712.4
  Bottom Layer w12: R203.1@1600,1740 1611.65,1740 v1(1621.65,1730)
NetR205_1: R205.1 U19.10 | length 1457
  Top Layer w6: U19.10@1314.57,2422.91 1314.57,2431.22 1333.35,2450 v1(1365,2450)
  SIGNAL LAYER w6: v1(897.24,1962.96) 1023.86,1962.96 1330.2,2269.3 1330.2,2415.2 v1(1365,2450)
  SIGNAL/POWER LAYER w6: v1(897.24,1962.96) 897.24,1886.35 897.24,1649.92 v1(1107.17,1440)
  Bottom Layer w6: v1(1107.17,1440) R205.1@1132.76,1440
NetR206_1: R206.1 U19.3 | length 298.9
  Top Layer w6: U19.3@1350,2269.37 1401.5,2269.37 1460.87,2210 1506.54,2210 1541.73,2174.81 1541.73,2152.23 1510,2120.5 R206.1@1510,2120
NetR209_1: R209.1 U19.1 | length 186.4
  Top Layer w6: U19.1@1350,2230 1378.63,2230 1443.04,2165.59 v1(1480,2165.59)
  Bottom Layer w6: v1(1480,2165.59) 1480,2150 R209.1@1490,2140
NetR210_1: R210.1 U19.36 | length 263.7
  Top Layer w6: U19.36@1314.57,2194.57 1314.57,2183.94 1315,2183.51 1315,2176.94 1355.91,2136.03 1355.91,2063.83 v1(1379.74,2040)
  Bottom Layer w6: v1(1379.74,2040) 1387.24,2040 R210.1@1440,2092.76
NetR220_2: R220.2 U10.14 | length 114.9
  Bottom Layer w10: U10.14@5398.97,2782.62 5439.43,2782.62 5491.35,2730.7 R220.2@5492.33,2730.7
NetR229_2: R229.2 U10.13 | length 100.3
  Bottom Layer w10: U10.13@5398.97,2808.21 5440.03,2808.21 5456.73,2791.5 R229.2@5492.33,2791.5
NetR230_2: R230.2 U10.11 | length 95.1
  Bottom Layer w10: U10.11@5398.97,2859.39 5402.83,2863.25 5429.49,2863.25 5459.13,2892.89 5459.13,2894.55 R230.2@5472.83,2908.25
NetR259_1: R259.1 S1.1 U29.3 | length 237.7
  Top Layer w10: S1.1@600,244.09 625,269.09 v1(769.88,269.09) 775,274.21 U29.3@775,294.36
  Bottom Layer w10: v1(769.88,269.09) R259.1@800,269.09
NetR260_2: R260.2 R261.2 U29.1 | length 124.6
  Top Layer w10: v1(750.59,390.75) 772.18,369.16 U29.1@775,369.16
  Bottom Layer w10: R261.2@725,369.09 728.94,369.09 v1(750.59,390.75) 771.57,369.76 R260.2@798.62,369.76
NetR269_1: R269.1 U31.2 | length 110.1
  Top Layer w6: v1(3204.04,361.56) 3213.61,351.99 U31.2@3213.61,302.7
  Bottom Layer w6: R269.1@3163.62,345 3187.48,345 v1(3204.04,361.56)
NetR280_2: R280.2 R320.2 U13.17 | length 235.9
  Top Layer w6: R280.2@2120,2426.06 2152.87,2426.06 2157.69,2430.88 v1@2164.07,2430.88 ; v1(2170.94,2430.88) v1@2164.07,2430.88 ; U13.17@2276.77,2422.91 2276.77,2435.47 2266.15,2446.09 2241.09,2446.09 2225,2430 2163.19,2430 v1@2164.07,2430.88
  Bottom Layer w6: R320.2@2129.34,2437.97 2163.85,2437.97 v1(2170.94,2430.88)
NetR282_2: R282.2 R322.2 U19.17 | length 220
  Top Layer w6: R282.2@1020.13,2426.19 1027.13,2433.19 v1(1060,2433.19) 1063.19,2430 1105.08,2430 1121.17,2446.09 1166.15,2446.09 1176.77,2435.47 U19.17@1176.77,2422.91
  Bottom Layer w6: R322.2@1030,2420 1046.81,2420 v1(1060,2433.19)
NetR340_1: R340.1 U1.20 | length 133.6
  Top Layer w6: v1(3247.42,2365) 3266.72,2365 3281.72,2380 3298.28,2380 3310,2368.28 3310,2367.79 U1.20@3321.65,2367.79
  Bottom Layer w6: R340.1@3206.62,2348.11 3230.53,2348.11 v1(3247.42,2365)
NetR348_1: R348.1 U7.20 | length 87.1
  Top Layer w6: v1(4380,2385) 4376.86,2385 4380,2381.86 4393.74,2381.86 4407.8,2367.79 U7.20@4421.65,2367.79
  Bottom Layer w6: R348.1@4350,2390 4375,2390 v1(4380,2385)
NetR361_2: R361.2 STRP_1.1 | length 598.9
  Bottom Layer w8: STRP_1.1@2903.53,2723.67 2903.53,2680.1 3011.04,2572.6 3047.84,2572.6 3187.98,2572.6 3220.38,2605 3347.55,2605 3382.48,2570.07 R361.2@3382.48,2566.14
NetR365_2: R365.2 STRP_1_2.1 | length 232.4
  Bottom Layer w8: STRP_1_2.1@4316.08,2706.5 4359.45,2706.5 R365.2@4493.11,2572.84
NetR404_2: R404.2 STRP1.1 | length 84.7
  Top Layer w6: R404.2@3980.09,2447.77 STRP1.1@3980.09,2532.48
P0-R1-RCLK: J2.73 R158.2 | length 2057.6
  Top Layer w6: v1(2035.59,1120) 2030,1125.59 2030,1151.59 ccw(c2030,1164.59) 2030,1177.59 cw(c2030,1190.59) 2030,1203.59 ccw(c2030,1216.59) 2030,1229.59 cw(c2030,1242.59) 2030,1255.59 ccw(c2030,1268.59) 2030,1281.59 cw(c2030,1294.59) 2030,1307.59 ccw(c2030,1320.59) 2030,1333.59 cw(c2030,1346.59) 2030,1359.59 ccw(c2030,1372.59) 2030,1385.59 cw(c2030,1398.59) 2030,1411.59 ccw(c2030,1424.59) 2030,1437.59 cw(c2030,1450.59) 2030,1463.59 ccw(c2030,1476.59) 2030,1489.59 cw(c2030,1502.59) 2030,1515.59 ccw(c2030,1528.59) 2030,1541.59 cw(c2030,1554.59) 2030,1567.59 ccw(c2030,1580.59) 2030,1593.59 cw(c2030,1606.59) 2030,1619.59 ccw(c2030,1632.59) 2030,1645.59 cw(c2030,1658.59) 2030,1671.59 ccw(c2030,1684.59) 2030,1697.59 cw(c2030,1710.59) 2030,1723.59 ccw(c2030,1736.59) 2030,1749.59 cw(c2030,1762.59) 2030,1775.59 ccw(c2030,1788.59) 2030,1801.59 cw(c2030,1814.59) 2030,1827.59 ccw(c2030,1840.59) 2030,1853.59 cw(c2030,1866.59) 2030,1879.59 ccw(c2030,1892.59) 2030,1905.59 cw(c2030,1918.59) 2030,1931.59 ccw(c2030,1944.59) 2030,1957.59 cw(c2030,1970.59) 2030,1983.59 ccw(c2030,1996.59) 2030,2009.59 cw(c2030,2022.59) 2030,2035.59 2030,2061.59 2030,2063.6 2030,2077.24 R158.2@2092.76,2140
  Bottom Layer w6: J2.73@1902.76,725 1902.76,795.68 1930.14,823.06 1947.56,823.06 2035.59,911.09 2035.59,999.4 2035.59,1014.8 ccw(c2035.59,1027.8) 2035.59,1040.8 cw(c2035.59,1053.8) 2035.59,1066.8 ccw(c2035.59,1079.8) 2035.59,1092.8 v1(2035.59,1120)
P0-R1-RCTL: J2.71 R159.2 | length 1960.4
  Top Layer w6: v1(1931.87,790) 1873.13,848.74 1873.13,1003.86 1842.48,1034.51 1842.48,2365.24 1953.99,2476.74 2066.01,2476.74 R159.2@2072.76,2470
  Bottom Layer w6: J2.71@1922.44,725 1922.44,780.57 v1(1931.87,790)
P0-R1-RD0: J2.69 R160.2 | length 2073.8
  Top Layer w6: v1(2070,1052.23) 1990,1132.23 1990,1140 1990,1166 ccw(c1990,1179) 1990,1192 cw(c1990,1205) 1990,1218 ccw(c1990,1231) 1990,1244 cw(c1990,1257) 1990,1270 ccw(c1990,1283) 1990,1296 cw(c1990,1309) 1990,1322 ccw(c1990,1335) 1990,1348 cw(c1990,1361) 1990,1374 ccw(c1990,1387) 1990,1400 cw(c1990,1413) 1990,1426 ccw(c1990,1439) 1990,1452 cw(c1990,1465) 1990,1478 ccw(c1990,1491) 1990,1504 cw(c1990,1517) 1990,1530 ccw(c1990,1543) 1990,1556 cw(c1990,1569) 1990,1582 ccw(c1990,1595) 1990,1608 cw(c1990,1621) 1990,1634 ccw(c1990,1647) 1990,1660 cw(c1990,1673) 1990,1686 ccw(c1990,1699) 1990,1712 cw(c1990,1725) 1990,1738 ccw(c1990,1751) 1990,1764 cw(c1990,1777) 1990,1790 ccw(c1990,1803) 1990,1816 cw(c1990,1829) 1990,1842 ccw(c1990,1855) 1990,1868 cw(c1990,1881) 1990,1894 ccw(c1990,1907) 1990,1920 cw(c1990,1933) 1990,1946 ccw(c1990,1959) 1990,1972 cw(c1990,1985) 1990,1998 1990,2024 1990,2103.2 2026.1,2139.3 2042.7,2139.3 2083.4,2180 R160.2@2092.76,2180
  Bottom Layer w6: J2.69@1942.13,725 1942.13,760.93 2070,888.8 v1(2070,1052.23)
P0-R1-RD1: J2.77 R161.2 | length 2095.9
  Top Layer w6: v1(1957.28,1120) 1957.28,1143.22 1941.1,1159.4 1941.1,1175 1950,1183.9 1950,1209.9 ccw(c1950,1222.9) 1950,1235.9 cw(c1950,1248.9) 1950,1261.9 ccw(c1950,1274.9) 1950,1287.9 cw(c1950,1300.9) 1950,1313.9 ccw(c1950,1326.9) 1950,1339.9 cw(c1950,1352.9) 1950,1365.9 ccw(c1950,1378.9) 1950,1391.9 cw(c1950,1404.9) 1950,1417.9 ccw(c1950,1430.9) 1950,1443.9 cw(c1950,1456.9) 1950,1469.9 ccw(c1950,1482.9) 1950,1495.9 cw(c1950,1508.9) 1950,1521.9 ccw(c1950,1534.9) 1950,1547.9 cw(c1950,1560.9) 1950,1573.9 ccw(c1950,1586.9) 1950,1599.9 cw(c1950,1612.9) 1950,1625.9 ccw(c1950,1638.9) 1950,1651.9 cw(c1950,1664.9) 1950,1677.9 ccw(c1950,1690.9) 1950,1703.9 cw(c1950,1716.9) 1950,1729.9 ccw(c1950,1742.9) 1950,1755.9 cw(c1950,1768.9) 1950,1781.9 ccw(c1950,1794.9) 1950,1807.9 cw(c1950,1820.9) 1950,1833.9 ccw(c1950,1846.9) 1950,1859.9 cw(c1950,1872.9) 1950,1885.9 ccw(c1950,1898.9) 1950,1911.9 cw(c1950,1924.9) 1950,1937.9 ccw(c1950,1950.9) 1950,1963.9 cw(c1950,1976.9) 1950,1989.9 ccw(c1950,2002.9) 1950,2015.9 cw(c1950,2028.9) 1950,2041.9 1950,2049.5 1950,2107.23 2036.72,2193.94 2065,2193.94 2091.05,2220 R161.2@2092.76,2220
  Bottom Layer w6: J2.77@1863.39,725 1863.39,811.2 1957.28,905.1 v1(1957.28,1120)
P0-R1-RD2: J2.75 R162.2 | length 2105.6
  Top Layer w6: v1(1991.34,1030) 1910,1111.33 1910,1140 1910,1166 ccw(c1910,1179) 1910,1192 cw(c1910,1205) 1910,1218 ccw(c1910,1231) 1910,1244 cw(c1910,1257) 1910,1270 ccw(c1910,1283) 1910,1296 cw(c1910,1309) 1910,1322 ccw(c1910,1335) 1910,1348 cw(c1910,1361) 1910,1374 ccw(c1910,1387) 1910,1400 cw(c1910,1413) 1910,1426 ccw(c1910,1439) 1910,1452 cw(c1910,1465) 1910,1478 ccw(c1910,1491) 1910,1504 cw(c1910,1517) 1910,1530 ccw(c1910,1543) 1910,1556 cw(c1910,1569) 1910,1582 ccw(c1910,1595) 1910,1608 cw(c1910,1621) 1910,1634 ccw(c1910,1647) 1910,1660 cw(c1910,1673) 1910,1686 ccw(c1910,1699) 1910,1712 cw(c1910,1725) 1910,1738 ccw(c1910,1751) 1910,1764 cw(c1910,1777) 1910,1790 ccw(c1910,1803) 1910,1816 cw(c1910,1829) 1910,1842 ccw(c1910,1855) 1910,1868 1910,1880.5 1910,2089.8 2027.14,2206.94 2055.15,2206.94 2061.15,2212.95 2061.15,2230.1 R162.2@2091.05,2260
  Bottom Layer w6: J2.75@1883.07,725 1883.07,804.38 1991.34,912.64 v1(1991.34,1030)
P0-R1-RD3: J2.79 R163.2 | length 2112.4
  Top Layer w6: v1(1930,910) 1930,1034.27 1870,1094.27 1870,1361.9 1870,1387.9 ccw(c1870,1400.9) 1870,1413.9 cw(c1870,1426.9) 1870,1439.9 ccw(c1870,1452.9) 1870,1465.9 cw(c1870,1478.9) 1870,1491.9 ccw(c1870,1504.9) 1870,1517.9 cw(c1870,1530.9) 1870,1543.9 ccw(c1870,1556.9) 1870,1569.9 cw(c1870,1582.9) 1870,1595.9 ccw(c1870,1608.9) 1870,1621.9 cw(c1870,1634.9) 1870,1647.9 ccw(c1870,1660.9) 1870,1673.9 cw(c1870,1686.9) 1870,1699.9 ccw(c1870,1712.9) 1870,1725.9 cw(c1870,1738.9) 1870,1751.9 ccw(c1870,1764.9) 1870,1777.9 cw(c1870,1790.9) 1870,1803.9 ccw(c1870,1816.9) 1870,1829.9 cw(c1870,1842.9) 1870,1855.9 ccw(c1870,1868.9) 1870,1881.9 cw(c1870,1894.9) 1870,1907.9 ccw(c1870,1920.9) 1870,1933.9 cw(c1870,1946.9) 1870,1959.9 ccw(c1870,1972.9) 1870,1985.9 cw(c1870,1998.9) 1870,2011.9 1870,2022.59 1870,2125.6 1999.4,2255 2043.28,2255 2088.28,2300 R163.2@2092.76,2300
  Bottom Layer w6: J2.79@1843.7,725 1843.7,823.7 v1(1930,910)
P0-R1-TCLK: J2.80 RN3.2 | length 81.7
  Top Layer w6: v1(1841.89,524.84) 1853.13,513.6 RN3.2@1853.13,494.09
  Bottom Layer w6: v1@1840,526.73 v1(1841.89,524.84) 1843.7,523.03 J2.80@1843.7,482.01
P0-R1-TCTL: J2.74 RN3.5 | length 100.8
  Top Layer w6: v1(1902.76,439.62) 1912.18,449.05 RN3.5@1912.18,494.09
  Bottom Layer w6: v1(1902.76,439.62) J2.74@1902.76,482.01
P0-R1-TD0: J2.72 RN3.6 | length 81.5
  Top Layer w6: v1@1925,527.07 v1(1925.76,526.31) 1931.87,520.2 RN3.6@1931.87,494.09
  Bottom Layer w6: J2.72@1922.44,482.01 1922.44,522.98 v1(1925.76,526.31)
P0-R1-TD1: J2.70 RN3.7 | length 100
  Top Layer w6: v1(1942.13,440) 1951.56,449.43 RN3.7@1951.56,494.09
  Bottom Layer w6: v1(1942.13,440) J2.70@1942.13,482.01
P0-R1-TD2: J2.78 RN3.3 | length 100
  Top Layer w6: v1(1863.39,440) 1872.82,449.43 RN3.3@1872.82,494.09
  Bottom Layer w6: v1(1863.39,440) J2.78@1863.39,482.01
P0-R1-TD3: J2.76 RN3.4 | length 80.4
  Top Layer w6: v1(1888.47,526.31) 1892.5,522.27 RN3.4@1892.5,494.09
  Bottom Layer w6: J2.76@1883.07,482.01 1883.07,517.12 1888.47,522.52 v1(1888.47,526.31)
P0-R2-RCLK: J2.7 R211.2 | length 4834.7
  Top Layer w6: R211.2@982.76,2140 982.76,2055.46 962.6,2035.3 878.06,2035.3 850,2007.24 850,1980 850,1972 ccw(c850,1959) 850,1946 cw(c850,1933) 850,1920 ccw(c850,1907) 850,1894 cw(c850,1881) 850,1868 ccw(c850,1855) 850,1842 cw(c850,1829) 850,1816 ccw(c850,1803) 850,1790 cw(c850,1777) 850,1764 ccw(c850,1751) 850,1738 cw(c850,1725) 850,1712 ccw(c850,1699) 850,1686 cw(c850,1673) 850,1660 ccw(c850,1647) 850,1634 cw(c850,1621) 850,1608 ccw(c850,1595) 850,1582 cw(c850,1569) 850,1556 ccw(c850,1543) 850,1530 cw(c850,1517) 850,1504 ccw(c850,1491) 850,1478 cw(c850,1465) 850,1452 ccw(c850,1439) 850,1426 cw(c850,1413) 850,1400 ccw(c850,1387) 850,1374 cw(c850,1361) 850,1348 ccw(c850,1335) 850,1322 cw(c850,1309) 850,1296 ccw(c850,1283) 850,1270 cw(c850,1257) 850,1244 ccw(c850,1231) 850,1218 cw(c850,1205) 850,1192 ccw(c850,1179) 850,1166 cw(c850,1153) 850,1140 ccw(c850,1127) 850,1114 cw(c850,1101) 850,1088 ccw(c850,1075) 850,1062 cw(c847.23,1049) 850,1036 850,1010 880.1,979.9 898.49,961.51 ccw(c907.68,952.32) 916.87,943.13 cw(c926.07,933.93) 935.26,924.74 ccw(c944.45,915.55) 953.64,906.36 cw(c962.84,897.16) 972.03,887.97 ccw(c981.22,878.78) 990.41,869.59 cw(c999.6,860.39) 1008.8,851.2 ccw(c1017.99,842.01) 1027.18,832.82 cw(c1036.37,823.63) 1045.57,814.43 ccw(c1054.76,805.24) 1063.95,796.05 cw(c1073.14,786.86) 1082.34,777.66 ccw(c1091.53,768.47) 1100.72,759.28 1115.2,744.8 1117.3,742.7 1117.3,533.1 1452.05,198.35 v1(1840,198.35) ; v1(2127,117) 2234.11,117 2271.81,79.3 2475.7,79.3 2514.18,117.78 2514.18,295.1 2578.03,358.95 2578.03,384.32 2618.72,425 2618.72,565.73 2646.57,593.58 2666.81,593.58 2705.9,632.67 2705.9,642 2744.96,681.06 v1(2749.21,681.06)
  Bottom Layer w6: v1(1840,198.35) 1912.95,125.4 2104.6,125.4 2113,117 v1(2127,117) ; v1(2749.21,681.06) J2.7@2749.21,725
P0-R2-RCTL: J2.11 R212.2 | length 4864
  Top Layer w6: R212.2@972.76,2470 972.76,2473.97 923.35,2523.38 813.78,2523.38 701.05,2410.65 701.05,2264.67 645,2208.62 645,815 1380,80 2018,80 2075.82,137.82 2246.29,137.82 2283.73,100.38 2465.63,100.38 2501.18,135.93 2501.18,300.49 2565.03,364.34 2565.03,389.7 2605.72,430.38 2605.72,571.11 2641.18,606.58 2661.42,606.58 2692.9,638.05 2692.9,656.03 2710,673.13 v1(2710,680.28)
  Bottom Layer w6: J2.11@2709.84,725 2709.84,680.43 v1(2710,680.28)
P0-R2-RD0: J2.13 R213.2 | length 4966.5
  Top Layer w6: R213.2@982.76,2180 981.05,2180 810,2008.94 810,1980 cw(c810,1967) 810,1954 ccw(c810,1941) 810,1928 cw(c810,1915) 810,1902 ccw(c810,1889) 810,1876 cw(c810,1863) 810,1850 ccw(c810,1837) 810,1824 cw(c810,1811) 810,1798 ccw(c810,1785) 810,1772 cw(c810,1759) 810,1746 ccw(c810,1733) 810,1720 cw(c810,1707) 810,1694 ccw(c810,1681) 810,1668 cw(c810,1655) 810,1642 ccw(c810,1629) 810,1616 cw(c810,1603) 810,1590 ccw(c810,1577) 810,1564 cw(c810,1551) 810,1538 ccw(c810,1525) 810,1512 cw(c810,1499) 810,1486 ccw(c810,1473) 810,1460 cw(c810,1447) 810,1434 ccw(c810,1421) 810,1408 cw(c810,1395) 810,1382 ccw(c810,1369) 810,1356 cw(c810,1343) 810,1330 ccw(c810,1317) 810,1304 cw(c810,1291) 810,1278 ccw(c810,1265) 810,1252 cw(c810,1239) 810,1226 ccw(c810,1213) 810,1200 cw(c810,1187) 810,1174 ccw(c810,1161) 810,1148 cw(c810,1135) 810,1122 ccw(c810,1109) 810,1096 cw(c810,1083) 810,1070 ccw(c810,1057) 810,1044 cw(c810,1031) 810,1018 ccw(c810,1005) 810,992 810,990 820,980 cw(c829.19,970.81) 838.38,961.61 ccw(c847.58,952.42) 856.77,943.23 cw(c865.96,934.04) 875.15,924.85 ccw(c884.35,915.65) 893.54,906.46 cw(c902.73,897.27) 911.92,888.08 ccw(c921.12,878.88) 930.31,869.69 cw(c939.5,860.5) 948.69,851.31 ccw(c957.89,842.11) 967.08,832.92 cw(c976.27,823.73) 985.46,814.54 ccw(c994.66,805.34) 1003.85,796.15 cw(c1013.04,786.96) 1022.23,777.77 1040,760 1092.3,707.7 1092.3,499.7 1125.7,465.1 1144.08,446.71 ccw(c1153.28,437.52) 1162.47,428.33 cw(c1171.66,419.14) 1180.85,409.95 ccw(c1190.05,400.75) 1199.24,391.56 cw(c1208.43,382.37) 1217.62,373.18 ccw(c1226.82,363.98) 1236.01,354.79 cw(c1245.2,345.6) 1254.39,336.41 ccw(c1263.59,327.21) 1272.78,318.02 cw(c1281.97,308.83) 1291.16,299.64 ccw(c1300.36,290.44) 1309.55,281.25 cw(c1318.74,272.06) 1327.93,262.87 ccw(c1337.12,253.67) 1346.32,244.48 cw(c1355.51,235.29) 1364.7,226.1 1368.3,222.5 1420.29,170.51 1947.37,170.51 1965.56,188.7 2104.7,188.7 2291.75,375.75 2376.3,375.75 2387.05,365 2488.03,365 2491.47,361.56 2524.84,361.56 2539.03,375.75 2539.03,400.47 2579.72,441.15 2579.72,581.88 2630.41,632.58 2630.41,648.24 2690.87,708.7 v1(2690.87,774.38)
  Bottom Layer w6: J2.13@2690.16,725 2690.16,773.66 v1(2690.87,774.38)
P0-R2-RD1: J2.15 R214.2 | length 4868.6
  Top Layer w6: R214.2@982.76,2220 981.05,2220 893.55,2132.5 836.9,2132.5 770,2065.6 770,1740.3 770,1724 ccw(c770,1711) 770,1698 cw(c770,1685) 770,1672 ccw(c770,1659) 770,1646 cw(c770,1633) 770,1620 ccw(c770,1607) 770,1594 cw(c770,1581) 770,1568 ccw(c770,1555) 770,1542 cw(c770,1529) 770,1516 ccw(c770,1503) 770,1490 cw(c770,1477) 770,1464 ccw(c770,1451) 770,1438 cw(c770,1425) 770,1412 ccw(c770,1399) 770,1386 cw(c770,1373) 770,1360 ccw(c770,1347) 770,1334 cw(c770,1321) 770,1308 ccw(c770,1295) 770,1282 cw(c770,1269) 770,1256 ccw(c770,1243) 770,1230 cw(c770,1217) 770,1204 ccw(c770,1191) 770,1178 cw(c770,1165) 770,1152 ccw(c770,1139) 770,1126 cw(c770,1113) 770,1100 ccw(c770,1087) 770,1074 cw(c770,1061) 770,1048 ccw(c770,1035) 770,1022 cw(c770,1009) 770,996 770,970 788.38,951.61 ccw(c797.58,942.42) 806.77,933.23 cw(c815.96,924.04) 825.15,914.85 ccw(c834.35,905.65) 843.54,896.46 cw(c852.73,887.27) 861.92,878.08 ccw(c871.12,868.88) 880.31,859.69 cw(c889.5,850.5) 898.69,841.31 ccw(c907.89,832.11) 917.08,822.92 cw(c926.27,813.73) 935.46,804.54 ccw(c944.66,795.34) 953.85,786.15 cw(c963.04,776.96) 972.23,767.77 ccw(c981.42,758.57) 990.62,749.38 cw(c999.81,740.19) 1009,731 ccw(c1018.19,721.8) 1027.39,712.61 cw(c1036.58,703.42) 1045.77,694.23 1060,680 1060,654 cw(c1060,641) 1060,628 ccw(c1064.12,615) 1060,602 cw(c1060,589) 1060,576 ccw(c1068.57,563) 1060,550 cw(c1060,537) 1060,524 1060,498 1060,490 1078.38,471.61 1079.52,470.48 1404.21,145.79 1980.35,145.79 v1(2000,165.44) ; v1(2000,222.88) 2044.17,222.88 2063.65,203.4 2095.4,203.4 2137.2,245.2 2137.2,277.1 2171.9,311.8 2194.6,311.8 2222.05,339.25 2222.05,350.15 2260.65,388.75 2381.68,388.75 2392.43,378 2493.42,378 2496.86,374.56 2510.84,374.56 2526.03,389.75 2526.03,405.86 2566.72,446.54 2566.72,587.26 2600,620.55 v1(2600,635)
  Bottom Layer w6: v1(2000,165.44) v1(2000,222.88) ; v1(2600,635) 2640.52,635 2670.47,664.95 J2.15@2670.47,725
P0-R2-RD2: J2.17 R215.2 | length 4874.8
  Top Layer w6: R215.2@982.76,2260 981.05,2260 881.79,2160.73 881.79,2160.62 872.17,2151 747.6,2151 730,2133.4 730,1920.6 730,1916.9 730,1906.5 730,1880.5 ccw(c730,1867.5) 730,1854.5 cw(c730,1841.5) 730,1828.5 ccw(c730,1815.5) 730,1802.5 cw(c730,1789.5) 730,1776.5 ccw(c730,1763.5) 730,1750.5 cw(c730,1737.5) 730,1724.5 ccw(c730,1711.5) 730,1698.5 cw(c730,1685.5) 730,1672.5 ccw(c730,1659.5) 730,1646.5 cw(c730,1633.5) 730,1620.5 ccw(c730,1607.5) 730,1594.5 cw(c730,1581.5) 730,1568.5 ccw(c730,1555.5) 730,1542.5 cw(c730,1529.5) 730,1516.5 ccw(c730,1503.5) 730,1490.5 cw(c730,1477.5) 730,1464.5 ccw(c730,1451.5) 730,1438.5 cw(c730,1425.5) 730,1412.5 ccw(c730,1399.5) 730,1386.5 cw(c730,1373.5) 730,1360.5 ccw(c730,1347.5) 730,1334.5 cw(c730,1321.5) 730,1308.5 ccw(c730,1295.5) 730,1282.5 cw(c730,1269.5) 730,1256.5 ccw(c730,1243.5) 730,1230.5 cw(c730,1217.5) 730,1204.5 ccw(c730,1191.5) 730,1178.5 cw(c730,1165.5) 730,1152.5 ccw(c730,1139.5) 730,1126.5 cw(c730,1113.5) 730,1100.5 ccw(c730,1087.5) 730,1074.5 cw(c730,1061.5) 730,1048.5 ccw(c730,1035.5) 730,1022.5 cw(c730,1009.5) 730,996.5 ccw(c730,983.5) 730,970.5 cw(c730,957.5) 730,944.5 730,918.5 730,790 1395.64,124.36 1994.36,124.36 v1(2030,160) ; v1(2073.44,223.44) 2073.44,241.54 2178.43,346.53 2178.43,374.46 2205.29,401.32 2242.88,401.32 2255.56,414 2374.82,414 2387.82,401 2479.44,401 2494.44,416 2511.53,416 2553.72,458.18 2553.72,592.65 2577,615.93 2577,649.6 2627.88,700.48 2639.8,700.48 2664.27,724.95 2664.27,762.56 2658.98,767.85 v1(2654.73,767.85)
  Bottom Layer w6: v1(2030,160) 2030,180 v1(2073.44,223.44) ; J2.17@2650.79,725 v1@2650.79,760.85
P0-R2-RD3: J2.9 R216.2 | length 5002.7
  Top Layer w6: R216.2@982.76,2300 981.05,2300 882.15,2201.1 825,2201.1 798.3,2227.8 723.03,2227.8 690,2194.77 690,1590 690,1589.6 690,1563.6 cw(c690,1550.6) 690,1537.6 ccw(c690,1524.6) 690,1511.6 cw(c690,1498.6) 690,1485.6 ccw(c690,1472.6) 690,1459.6 cw(c690,1446.6) 690,1433.6 ccw(c690,1420.6) 690,1407.6 cw(c690,1394.6) 690,1381.6 ccw(c690,1368.6) 690,1355.6 cw(c690,1342.6) 690,1329.6 ccw(c690,1316.6) 690,1303.6 cw(c690,1290.6) 690,1277.6 ccw(c690,1264.6) 690,1251.6 cw(c690,1238.6) 690,1225.6 ccw(c690,1212.6) 690,1199.6 cw(c690,1186.6) 690,1173.6 ccw(c690,1160.6) 690,1147.6 cw(c690,1134.6) 690,1121.6 ccw(c690,1108.6) 690,1095.6 cw(c690,1082.6) 690,1069.6 ccw(c690,1056.6) 690,1043.6 cw(c690,1030.6) 690,1017.6 ccw(c690,1004.6) 690,991.6 cw(c690,978.6) 690,965.6 ccw(c690,952.6) 690,939.6 cw(c690,926.6) 690,913.6 690,887.6 690,799.72 1389.35,100.38 2015.43,100.38 2071.05,156 2227.8,156 2269.15,197.35 2269.15,285.15 2316.45,332.45 2404.2,332.45 2405,333.26 ; 2405,333.28 2416.72,345 2433.33,345 2453.53,324.8 2506.47,324.8 2552.03,370.36 2552.03,395.09 2592.72,435.77 2592.72,576.5 2635.8,619.58 2656.04,619.58 2679.9,643.44 2679.9,679.34 2719.26,718.7 2719.26,756.08 v1(2736.84,773.66)
  Bottom Layer w6: J2.9@2729.53,725 2729.53,764.21 2738.98,773.66 v1(2736.84,773.66)
P0-R2-TCLK: J2.87 RN4.13 | length 79.2
  Top Layer w6: v1(1764.31,770) 1773.7,760.61 RN4.13@1773.7,740
  Bottom Layer w6: v1(1764.31,770) 1764.96,769.35 J2.87@1764.96,725
P0-R2-TCTL: J2.91 RN4.11 | length 83
  Top Layer w6: v1(1733.7,770.54) 1733.7,770 1734.33,769.37 RN4.11@1734.33,740
  Bottom Layer w6: J2.91@1725.59,725 1725.59,768.03 1728.1,770.54 v1(1733.7,770.54)
P0-R2-TD0: J2.85 RN4.14 | length 108.3
  Top Layer w6: v1(1790,680.28) 1793.38,683.66 RN4.14@1793.38,740
  Bottom Layer w6: J2.85@1784.65,725.2 J2.85@1784.65,725 1784.65,685.63 v1(1790,680.28)
P0-R2-TD1: J2.83 RN4.15 | length 78.9
  Top Layer w6: v1(1804.33,770) 1813.07,761.26 RN4.15@1813.07,740
  Bottom Layer w6: J2.83@1804.33,724.7 J2.83@1804.33,725 v1(1804.33,770)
